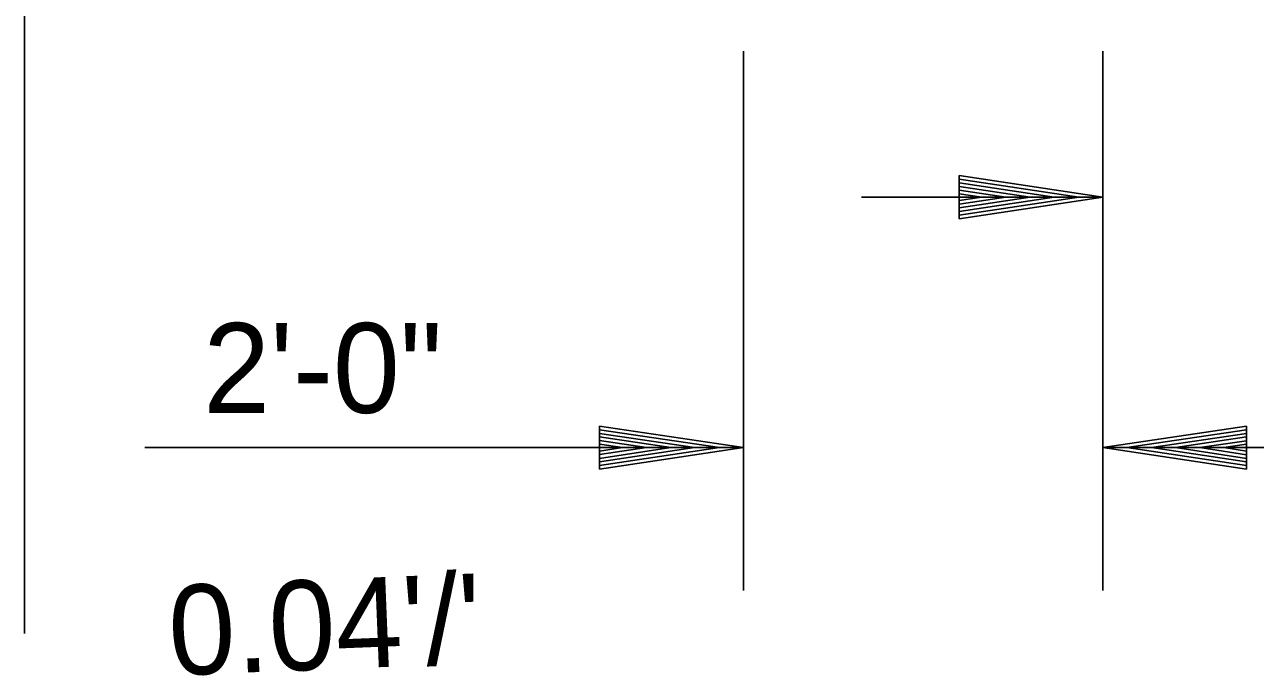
# Model space of a CAD drawing. Extents: x 60325 to 61047, y 53669 to 53767.
# Drawn here: x 60347.25 to 60354.1, y 53690.63 to 53694.16 of the extents above; entities that cross this region are included whole.
import ezdxf

# ---------------------------------------------------------------- set-up
doc = ezdxf.new("R2010")
doc.units = 0
doc.layers.add('R_Border', color=7, linetype='Continuous')
doc.layers.add('R_Border Prem', color=7, linetype='Continuous')

msp = doc.modelspace()

# ---------------------------------------------------------------- linework, layer by layer
at = {"layer": 'R_Border'}
for p, q in [((60353.2467, 53691.0151), (60353.2467, 53694.0151)), ((60352.4467, 53693.3225), (60353.2467, 53693.2025)), ((60352.4467, 53693.3225), (60352.4467, 53693.0825)), ((60352.4467, 53693.3025), (60353.1131, 53693.2025)), ((60352.4467, 53693.2821), (60352.9755, 53693.2025)), ((60352.4467, 53693.2621), (60352.8423, 53693.2025)), ((60352.4467, 53693.2413), (60352.7067, 53693.2025)), ((60353.2467, 53693.2025), (60351.9043, 53693.2025)), ((60352.4467, 53693.2213), (60352.5731, 53693.2025)), ((60352.4467, 53693.0825), (60353.2467, 53693.2025)), ((60352.4467, 53693.1633), (60352.7067, 53693.2025)), ((60352.4467, 53693.1229), (60352.9755, 53693.2025)), ((60352.4467, 53693.1025), (60353.1131, 53693.2025)), ((60352.4467, 53693.1429), (60352.8423, 53693.2025)), ((60352.4467, 53693.1837), (60352.5731, 53693.2025))]:
    msp.add_line(p, q, dxfattribs=at)
at = {"layer": 'R_Border Prem'}
for p, q in [((60347.2467, 53690.7751), (60347.2467, 53696.0114)), ((60351.2467, 53692.8037), (60351.2467, 53694.0151)), ((60351.2467, 53691.0151), (60351.2467, 53692.8037)), ((60350.4467, 53691.9292), (60351.2467, 53691.8092)), ((60350.4467, 53691.6892), (60350.4467, 53691.9292)), ((60350.4467, 53691.9092), (60351.1131, 53691.8092)), ((60350.4467, 53691.8888), (60350.9755, 53691.8092)), ((60350.4467, 53691.8688), (60350.8423, 53691.8092)), ((60354.0467, 53691.9292), (60353.2467, 53691.8092)), ((60354.0467, 53691.9092), (60353.3803, 53691.8092)), ((60354.0467, 53691.8888), (60353.5179, 53691.8092)), ((60354.0467, 53691.8688), (60353.6511, 53691.8092)), ((60354.0467, 53691.9292), (60354.0467, 53691.6892)), ((60351.2467, 53691.8092), (60347.9166, 53691.8092)), ((60350.4467, 53691.8484), (60350.7067, 53691.8092)), ((60350.4467, 53691.828), (60350.5731, 53691.8092)), ((60350.4467, 53691.6892), (60351.2467, 53691.8092)), ((60350.4467, 53691.7704), (60350.7067, 53691.8092)), ((60350.4467, 53691.7296), (60350.9755, 53691.8092)), ((60350.4467, 53691.7092), (60351.1131, 53691.8092)), ((60350.4467, 53691.7496), (60350.8423, 53691.8092)), ((60350.4467, 53691.7904), (60350.5731, 53691.8092)), ((60353.2467, 53691.8092), (60354.5891, 53691.8092)), ((60354.0467, 53691.6892), (60353.2467, 53691.8092)), ((60354.0467, 53691.7092), (60353.3803, 53691.8092)), ((60354.0467, 53691.7296), (60353.5179, 53691.8092)), ((60354.0467, 53691.7496), (60353.6511, 53691.8092)), ((60354.0467, 53691.848), (60353.7867, 53691.8092)), ((60354.0467, 53691.77), (60353.7867, 53691.8092)), ((60354.0467, 53691.828), (60353.9203, 53691.8092)), ((60354.0467, 53691.7904), (60353.9203, 53691.8092))]:
    msp.add_line(p, q, dxfattribs=at)

# ---------------------------------------------------------------- texts
msp.add_text('2\'-0"', height=0.5, dxfattribs=at).set_placement((60348.2407, 53692.0024))
msp.add_text("0.04'/'", height=0.5, rotation=2.29061, dxfattribs=at).set_placement((60348.0571, 53690.5415))

doc.saveas('drawing.dxf')
